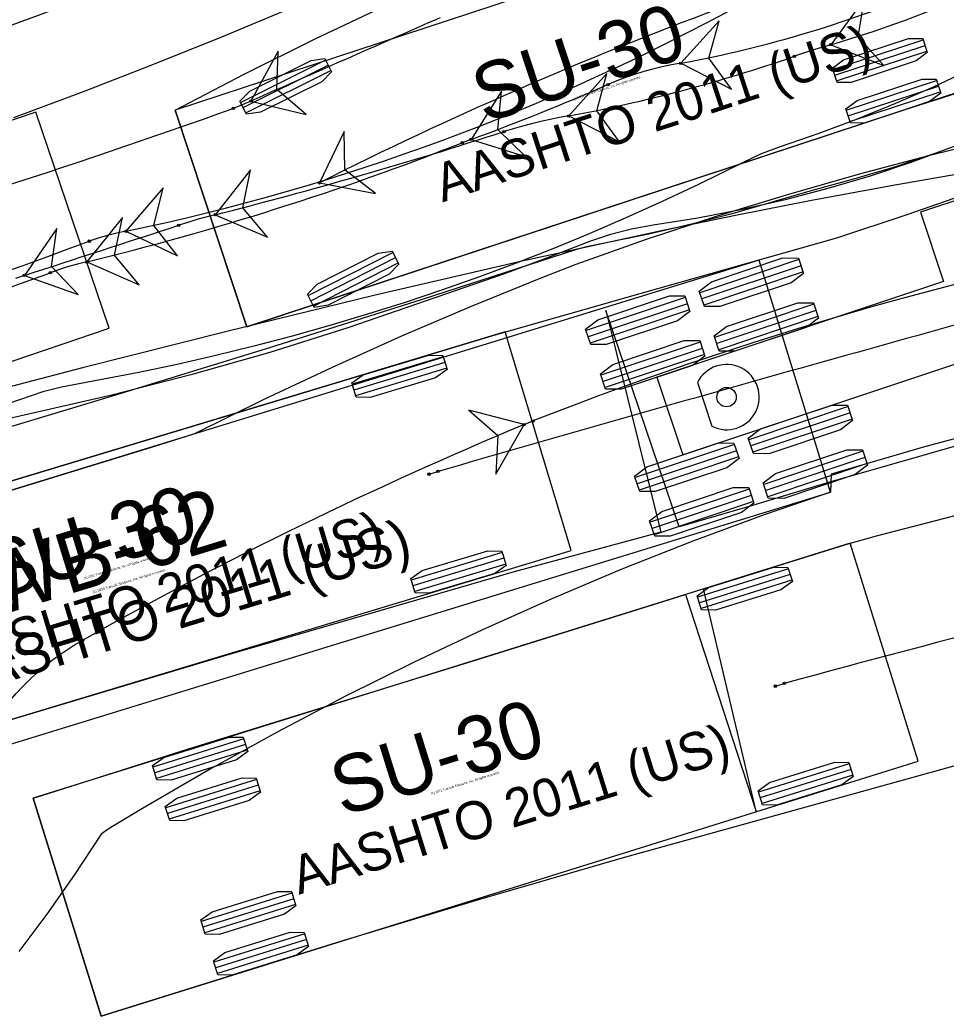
# Model space of a CAD drawing. Extents: x 2096670 to 2098561, y 684033 to 689893.
# Drawn here: x 2097637.92 to 2097670.38, y 685840.48 to 685875.39 of the extents above; entities that cross this region are included whole.
import ezdxf

# ---------------------------------------------------------------- set-up
doc = ezdxf.new("R2010")
doc.units = 0
doc.layers.add('Old_Level_63', color=7, linetype='Continuous')

msp = doc.modelspace()

# ---------------------------------------------------------------- linework, layer by layer
at = {"layer": 'Old_Level_63'}
for p, q in [((2097671.852, 685881.632), (2097643.364, 685872.228)), ((2097666.413, 685873.65), (2097669.578, 685874.695)), ((2097666.478, 685873.452), (2097669.644, 685874.497)), ((2097666.544, 685873.254), (2097669.709, 685874.299)), ((2097645.653, 685872.504), (2097648.635, 685873.995)), ((2097645.746, 685872.318), (2097648.728, 685873.809)), ((2097645.872, 685864.631), (2097674.359, 685874.036)), ((2097645.84, 685872.131), (2097648.821, 685873.622)), ((2097683.714, 685873.402), (2097669.485, 685868.655)), ((2097666.883, 685872.226), (2097670.049, 685873.271)), ((2097666.949, 685872.028), (2097670.114, 685873.073)), ((2097667.014, 685871.83), (2097670.179, 685872.875)), ((2097638.478, 685872.163), (2097610.065, 685862.533)), ((2097641.046, 685864.586), (2097638.478, 685872.163)), ((2097643.364, 685872.228), (2097645.872, 685864.631)), ((2097669.485, 685868.655), (2097670.298, 685866.221)), ((2097648.018, 685865.735), (2097650.989, 685867.246)), ((2097663.828, 685866.968), (2097617.949, 685852.856)), ((2097648.112, 685865.549), (2097651.083, 685867.061)), ((2097648.207, 685865.364), (2097651.178, 685866.875)), ((2097665.226, 685866.993), (2097661.748, 685865.832)), ((2097665.298, 685866.775), (2097661.82, 685865.615)), ((2097666.327, 685858.844), (2097663.828, 685866.968)), ((2097663.828, 685866.968), (2097663.828, 685866.968)), ((2097665.371, 685866.558), (2097661.893, 685865.397)), ((2097670.298, 685866.221), (2097660.242, 685862.866)), ((2097661.242, 685865.663), (2097657.763, 685864.503)), ((2097661.314, 685865.446), (2097657.836, 685864.286)), ((2097665.748, 685865.427), (2097662.27, 685864.267)), ((2097661.387, 685865.229), (2097657.909, 685864.068)), ((2097665.821, 685865.21), (2097662.342, 685864.05)), ((2097665.893, 685864.993), (2097662.415, 685863.832)), ((2097645.872, 685864.631), (2097645.872, 685864.631)), ((2097612.634, 685854.956), (2097641.046, 685864.586)), ((2097654.93, 685864.455), (2097626.208, 685855.794)), ((2097657.24, 685856.796), (2097654.93, 685864.455)), ((2097654.93, 685864.455), (2097654.93, 685864.455)), ((2097661.764, 685864.098), (2097658.286, 685862.938)), ((2097652.757, 685863.582), (2097649.565, 685862.62)), ((2097661.836, 685863.881), (2097658.358, 685862.721)), ((2097661.909, 685863.664), (2097658.431, 685862.503)), ((2097652.817, 685863.383), (2097649.625, 685862.421)), ((2097661.15, 685860.147), (2097671.205, 685863.501)), ((2097652.877, 685863.183), (2097649.685, 685862.221)), ((2097660.242, 685862.866), (2097661.15, 685860.147)), ((2097661.666, 685862.682), (2097662.177, 685861.149)), ((2097666.945, 685861.839), (2097663.467, 685860.678)), ((2097667.018, 685861.621), (2097663.54, 685860.461)), ((2097667.09, 685861.404), (2097663.612, 685860.243)), ((2097662.961, 685860.509), (2097659.483, 685859.349)), ((2097663.034, 685860.292), (2097659.556, 685859.132)), ((2097667.467, 685860.273), (2097663.989, 685859.113)), ((2097663.106, 685860.075), (2097659.628, 685858.914)), ((2097667.54, 685860.056), (2097664.062, 685858.896)), ((2097667.613, 685859.839), (2097664.134, 685858.678)), ((2097620.448, 685844.731), (2097666.327, 685858.844)), ((2097663.483, 685858.944), (2097660.005, 685857.784)), ((2097663.556, 685858.727), (2097660.078, 685857.566)), ((2097663.628, 685858.509), (2097660.15, 685857.349)), ((2097667.021, 685857.05), (2097638.383, 685848.113)), ((2097669.404, 685849.413), (2097667.021, 685857.05)), ((2097667.021, 685857.05), (2097667.021, 685857.05)), ((2097628.517, 685848.135), (2097657.24, 685856.796)), ((2097654.826, 685856.721), (2097651.634, 685855.758)), ((2097654.886, 685856.521), (2097651.694, 685855.559)), ((2097654.946, 685856.322), (2097651.755, 685855.36)), ((2097664.856, 685856.156), (2097661.674, 685855.163)), ((2097664.918, 685855.957), (2097661.736, 685854.964)), ((2097664.98, 685855.758), (2097661.798, 685854.765)), ((2097645.764, 685850.198), (2097642.582, 685849.205)), ((2097645.826, 685849.999), (2097642.644, 685849.006)), ((2097645.888, 685849.8), (2097642.706, 685848.807)), ((2097640.766, 685840.476), (2097669.404, 685849.413)), ((2097666.991, 685849.315), (2097663.809, 685848.322)), ((2097667.053, 685849.116), (2097663.871, 685848.123)), ((2097667.115, 685848.917), (2097663.933, 685847.924)), ((2097646.211, 685848.766), (2097643.029, 685847.773)), ((2097646.273, 685848.567), (2097643.091, 685847.574)), ((2097646.335, 685848.368), (2097643.153, 685847.375)), ((2097638.383, 685848.113), (2097640.766, 685840.476)), ((2097647.452, 685844.788), (2097644.27, 685843.795)), ((2097647.514, 685844.59), (2097644.332, 685843.597)), ((2097647.576, 685844.391), (2097644.394, 685843.398)), ((2097647.899, 685843.357), (2097644.717, 685842.364)), ((2097647.961, 685843.158), (2097644.779, 685842.165)), ((2097648.023, 685842.959), (2097644.841, 685841.966))]:
    msp.add_line(p, q, dxfattribs=at)
for points in [[(2097611.027, 685865.635), (2097616.113, 685867.407), (2097621.195, 685869.216), (2097631.356, 685872.914), (2097644.361, 685877.697), (2097646.901, 685878.659), (2097649.442, 685879.648), (2097654.215, 685881.571), (2097654.52, 685881.765), (2097655.712, 685882.687), (2097656.916, 685883.581), (2097658.129, 685884.446), (2097659.355, 685885.285), (2097660.596, 685886.098), (2097661.228, 685886.456), (2097663.81, 685887.688), (2097665.447, 685888.429), (2097668.097, 685889.57), (2097670.755, 685890.808)], [(2097671.388, 685873.026), (2097668.614, 685872.139), (2097645.872, 685864.631), (2097643.364, 685872.228), (2097645.774, 685873.486), (2097648.27, 685874.728), (2097650.796, 685875.923), (2097653.348, 685877.068), (2097655.81, 685878.116), (2097657.667, 685878.87), (2097660.103, 685879.997), (2097662.573, 685881.082), (2097665.093, 685882.107), (2097666.681, 685882.712), (2097669.252, 685883.626), (2097671.875, 685884.477)], [(2097626.522, 685855.889), (2097654.577, 685864.349), (2097659.655, 685865.807), (2097666.553, 685867.754), (2097669.015, 685868.577), (2097671.467, 685869.43), (2097673.908, 685870.315), (2097676.337, 685871.231), (2097678.755, 685872.178), (2097681.16, 685873.156), (2097683.553, 685874.164), (2097685.932, 685875.203), (2097688.298, 685876.272), (2097690.65, 685877.371), (2097692.988, 685878.5), (2097695.311, 685879.658), (2097697.622, 685880.848), (2097699.9, 685882.058)], [(2097637.708, 685871.968), (2097640.151, 685872.882), (2097642.579, 685873.826), (2097644.994, 685874.802), (2097647.397, 685875.808)], [(2097666.338, 685874.522), (2097668.204, 685873.801), (2097667.298, 685874.804), (2097667.518, 685876.138), (2097666.338, 685874.522)], [(2097661.083, 685873.876), (2097662.863, 685872.963), (2097662.066, 685874.056), (2097662.425, 685875.359), (2097661.083, 685873.876)], [(2097666.338, 685874.522), (2097666.018, 685874.429), (2097665.7, 685874.33), (2097665.383, 685874.227), (2097665.068, 685874.118)], [(2097646.013, 685872.548), (2097647.956, 685872.075), (2097646.928, 685872.952), (2097646.973, 685874.303), (2097646.013, 685872.548)], [(2097661.083, 685873.876), (2097660.755, 685873.817), (2097660.429, 685873.748), (2097660.105, 685873.669), (2097659.783, 685873.581), (2097659.465, 685873.482), (2097659.15, 685873.373), (2097658.839, 685873.254), (2097658.531, 685873.125)], [(2097671.243, 685873.655), (2097669.927, 685873.036), (2097668.61, 685872.46), (2097667.266, 685871.914), (2097665.918, 685871.409), (2097664.567, 685870.943), (2097663.906, 685870.694), (2097663.272, 685870.401), (2097661.708, 685869.628), (2097660.431, 685869.026), (2097659.153, 685868.45), (2097657.874, 685867.899), (2097656.596, 685867.373), (2097655.316, 685866.871), (2097654.026, 685866.39), (2097652.727, 685865.93), (2097651.421, 685865.492), (2097650.107, 685865.075), (2097648.785, 685864.679), (2097647.457, 685864.306), (2097646.122, 685863.954), (2097644.781, 685863.625), (2097643.434, 685863.317), (2097642.086, 685863.033), (2097639.374, 685862.524), (2097638.715, 685862.356), (2097635.843, 685861.37)], [(2097657.157, 685872.027), (2097658.938, 685871.117), (2097658.141, 685872.208), (2097658.496, 685873.512), (2097657.157, 685872.027)], [(2097653.735, 685871.203), (2097655.644, 685870.607), (2097654.673, 685871.548), (2097654.804, 685872.893), (2097653.735, 685871.203)], [(2097646.013, 685872.548), (2097645.708, 685872.413), (2097645.398, 685872.29)], [(2097657.157, 685872.027), (2097656.829, 685871.967), (2097656.502, 685871.901), (2097656.177, 685871.829), (2097655.853, 685871.752), (2097655.53, 685871.667), (2097655.209, 685871.577), (2097654.89, 685871.48)], [(2097609.816, 685850.484), (2097612.285, 685851.185), (2097617.256, 685852.655), (2097642.794, 685860.498), (2097644.054, 685860.899), (2097646.457, 685862.084), (2097648.874, 685863.222), (2097651.305, 685864.315), (2097653.75, 685865.362), (2097656.192, 685866.356), (2097657.414, 685866.834), (2097659.884, 685867.703), (2097662.369, 685868.521), (2097664.87, 685869.29), (2097667.389, 685870.01), (2097669.951, 685870.687), (2097672.53, 685871.313)], [(2097699.852, 685871.449), (2097697.423, 685870.233), (2097694.979, 685869.049), (2097692.521, 685867.895), (2097690.047, 685866.773), (2097687.56, 685865.683), (2097685.058, 685864.625), (2097684.428, 685864.373), (2097666.174, 685859.152), (2097663.602, 685858.37), (2097661.028, 685857.622), (2097658.459, 685865.206), (2097660.383, 685857.44), (2097655.238, 685856.05), (2097645.059, 685853.086), (2097634.895, 685850.058), (2097628.517, 685848.135), (2097626.208, 685855.794), (2097626.522, 685855.889), (2097626.522, 685855.889)], [(2097648.416, 685869.683), (2097650.381, 685869.311), (2097649.309, 685870.134), (2097649.285, 685871.485), (2097648.416, 685869.683)], [(2097671.399, 685871.229), (2097669.99, 685870.706), (2097668.573, 685870.233), (2097667.142, 685869.806), (2097665.684, 685869.419), (2097662.839, 685868.59), (2097661.407, 685868.217), (2097659.964, 685867.879), (2097657.78, 685867.441), (2097657.427, 685867.351), (2097652.017, 685865.598), (2097646.662, 685863.902), (2097641.004, 685862.157), (2097635.721, 685860.567), (2097624.882, 685857.361), (2097614.448, 685854.31), (2097603.853, 685851.239)], [(2097670.627, 685870.948), (2097669.186, 685870.411), (2097667.723, 685869.921), (2097666.24, 685869.479), (2097664.747, 685869.087), (2097663.23, 685868.743), (2097661.682, 685868.446), (2097660.117, 685868.2), (2097659.353, 685868.056), (2097658.622, 685867.869), (2097657.921, 685867.638), (2097656.227, 685866.983), (2097654.863, 685866.479), (2097649.41, 685864.6), (2097646.672, 685863.74), (2097643.914, 685862.955), (2097641.139, 685862.245), (2097637.653, 685861.451), (2097632.385, 685859.681), (2097626.785, 685857.876), (2097621.955, 685856.294), (2097617.307, 685854.818), (2097607.866, 685851.921)], [(2097653.735, 685871.203), (2097653.422, 685871.088)], [(2097671.007, 685870.02), (2097668.46, 685869.577), (2097665.602, 685869.047), (2097663.062, 685868.548), (2097660.515, 685868.025), (2097655.42, 685866.916), (2097650.32, 685865.732), (2097645.215, 685864.488), (2097640.109, 685863.193), (2097634.659, 685861.768), (2097629.517, 685860.389), (2097624.381, 685858.979), (2097619.249, 685857.543), (2097614.121, 685856.081), (2097608.998, 685854.597)], [(2097644.763, 685868.564), (2097646.6, 685867.774), (2097645.732, 685868.81), (2097646.001, 685870.135), (2097644.763, 685868.564)], [(2097641.635, 685867.985), (2097643.438, 685867.119), (2097642.614, 685868.19), (2097642.939, 685869.502), (2097641.635, 685867.985)], [(2097640.263, 685866.913), (2097642.093, 685866.106), (2097641.234, 685867.15), (2097641.516, 685868.472), (2097640.263, 685866.913)], [(2097644.763, 685868.564), (2097644.44, 685868.482), (2097644.118, 685868.393), (2097643.799, 685868.297), (2097643.482, 685868.194)], [(2097638.076, 685866.438), (2097639.96, 685865.768), (2097639.027, 685866.746), (2097639.211, 685868.085), (2097638.076, 685866.438)], [(2097641.635, 685867.985), (2097641.309, 685867.917), (2097640.985, 685867.837), (2097640.665, 685867.744), (2097640.349, 685867.638)], [(2097638.686, 685848.207), (2097643.793, 685849.833), (2097653.955, 685852.972), (2097661.246, 685855.248), (2097663.729, 685847.642), (2097661.881, 685855.446), (2097666.982, 685857.038), (2097667.943, 685857.309), (2097673.099, 685858.643), (2097680.86, 685860.563), (2097685.962, 685862.09), (2097691.057, 685863.643), (2097696.413, 685865.306), (2097698.858, 685866.102), (2097701.265, 685866.944)], [(2097640.263, 685866.913), (2097639.939, 685866.835), (2097639.618, 685866.745), (2097639.3, 685866.644), (2097638.986, 685866.531)], [(2097638.076, 685866.438), (2097637.759, 685866.335)], [(2097655.591, 685861.207), (2097653.658, 685861.72), (2097654.668, 685860.822), (2097654.595, 685859.473), (2097655.591, 685861.207)], [(2097655.591, 685861.207), (2097655.899, 685861.335)], [(2097672.017, 685861.066), (2097669.543, 685860.405), (2097666.349, 685859.467), (2097666.327, 685858.844), (2097664.011, 685858.044), (2097661.508, 685857.12), (2097659.022, 685856.138), (2097656.56, 685855.103), (2097654.127, 685854.017), (2097651.711, 685852.875), (2097649.312, 685851.677), (2097646.93, 685850.424), (2097644.565, 685849.117), (2097642.216, 685847.755), (2097641.048, 685847.055), (2097640.764, 685846.854), (2097639.821, 685845.42), (2097638.859, 685844.05), (2097637.879, 685842.739)], [(2097652.256, 685859.471), (2097652.575, 685859.567)], [(2097703.484, 685858.863), (2097698.012, 685857.136), (2097692.848, 685855.535), (2097687.714, 685853.971), (2097659.06, 685846.025), (2097654.024, 685844.557), (2097648.998, 685843.039), (2097640.766, 685840.476), (2097638.383, 685848.113), (2097638.686, 685848.207), (2097638.686, 685848.207)], [(2097636.607, 685850.172), (2097636.782, 685850.456), (2097636.965, 685850.734), (2097637.158, 685851.006), (2097637.359, 685851.272), (2097637.569, 685851.531), (2097637.788, 685851.783), (2097638.015, 685852.027), (2097638.25, 685852.263), (2097638.494, 685852.49), (2097638.745, 685852.709), (2097639.005, 685852.918), (2097639.272, 685853.117), (2097639.547, 685853.306), (2097639.829, 685853.484), (2097640.118, 685853.65)], [(2097664.394, 685852.04), (2097664.713, 685852.139)]]:
    msp.add_lwpolyline(points, dxfattribs=at)
for points in [[(2097666.338, 685874.522), (2097668.204, 685873.801), (2097667.298, 685874.804), (2097667.518, 685876.138)], [(2097661.083, 685873.876), (2097662.863, 685872.963), (2097662.066, 685874.056), (2097662.425, 685875.359)], [(2097666.56, 685873.205), (2097666.397, 685873.699), (2097666.791, 685873.994), (2097669.07, 685874.747), (2097669.562, 685874.744), (2097669.725, 685874.25), (2097669.331, 685873.955), (2097667.052, 685873.203)], [(2097646.013, 685872.548), (2097647.956, 685872.075), (2097646.928, 685872.952), (2097646.973, 685874.303)], [(2097645.863, 685872.085), (2097645.63, 685872.55), (2097645.977, 685872.899), (2097648.124, 685873.973), (2097648.611, 685874.041), (2097648.844, 685873.576), (2097648.497, 685873.227), (2097646.35, 685872.154)], [(2097657.157, 685872.027), (2097658.938, 685871.117), (2097658.141, 685872.208), (2097658.496, 685873.512)], [(2097667.03, 685871.781), (2097666.867, 685872.275), (2097667.261, 685872.57), (2097669.54, 685873.322), (2097670.032, 685873.32), (2097670.195, 685872.826), (2097669.801, 685872.531), (2097667.522, 685871.778)], [(2097653.735, 685871.203), (2097655.644, 685870.607), (2097654.673, 685871.548), (2097654.804, 685872.893)], [(2097648.416, 685869.683), (2097650.381, 685869.311), (2097649.309, 685870.134), (2097649.285, 685871.485)], [(2097644.763, 685868.564), (2097646.6, 685867.774), (2097645.732, 685868.81), (2097646.001, 685870.135)], [(2097641.635, 685867.985), (2097643.438, 685867.119), (2097642.614, 685868.19), (2097642.939, 685869.502)], [(2097640.263, 685866.913), (2097642.093, 685866.106), (2097641.234, 685867.15), (2097641.516, 685868.472)], [(2097638.076, 685866.438), (2097639.96, 685865.768), (2097639.027, 685866.746), (2097639.211, 685868.085)], [(2097648.23, 685865.318), (2097647.994, 685865.781), (2097648.339, 685866.132), (2097650.478, 685867.22), (2097650.965, 685867.292), (2097651.201, 685866.829), (2097650.856, 685866.478), (2097648.717, 685865.39)], [(2097665.208, 685867.047), (2097665.389, 685866.504), (2097664.956, 685866.178), (2097662.452, 685865.343), (2097661.911, 685865.344), (2097661.73, 685865.886), (2097662.162, 685866.212), (2097664.666, 685867.048)], [(2097661.224, 685865.717), (2097661.405, 685865.175), (2097660.972, 685864.849), (2097658.468, 685864.013), (2097657.927, 685864.014), (2097657.746, 685864.557), (2097658.178, 685864.883), (2097660.682, 685865.718)], [(2097665.73, 685865.481), (2097665.911, 685864.939), (2097665.479, 685864.613), (2097662.974, 685863.777), (2097662.433, 685863.778), (2097662.252, 685864.321), (2097662.684, 685864.647), (2097665.189, 685865.482)], [(2097661.746, 685864.152), (2097661.927, 685863.61), (2097661.495, 685863.284), (2097658.99, 685862.448), (2097658.449, 685862.449), (2097658.268, 685862.992), (2097658.7, 685863.318), (2097661.204, 685864.153)], [(2097652.742, 685863.632), (2097652.892, 685863.134), (2097652.49, 685862.849), (2097650.192, 685862.156), (2097649.7, 685862.172), (2097649.55, 685862.669), (2097649.952, 685862.954), (2097652.25, 685863.647)], [(2097666.927, 685861.892), (2097667.108, 685861.35), (2097666.676, 685861.024), (2097664.172, 685860.188), (2097663.63, 685860.19), (2097663.449, 685860.732), (2097663.882, 685861.058), (2097666.386, 685861.894)], [(2097655.591, 685861.207), (2097653.658, 685861.72), (2097654.668, 685860.822), (2097654.595, 685859.473)], [(2097662.943, 685860.563), (2097663.124, 685860.021), (2097662.692, 685859.695), (2097660.188, 685858.859), (2097659.646, 685858.86), (2097659.465, 685859.403), (2097659.897, 685859.729), (2097662.402, 685860.564)], [(2097667.45, 685860.327), (2097667.631, 685859.785), (2097667.198, 685859.459), (2097664.694, 685858.623), (2097664.152, 685858.624), (2097663.971, 685859.167), (2097664.404, 685859.493), (2097666.908, 685860.328)], [(2097663.465, 685858.998), (2097663.646, 685858.456), (2097663.214, 685858.13), (2097660.71, 685857.294), (2097660.168, 685857.295), (2097659.987, 685857.838), (2097660.42, 685858.164), (2097662.924, 685858.999)], [(2097654.811, 685856.77), (2097654.961, 685856.272), (2097654.559, 685855.988), (2097652.261, 685855.295), (2097651.769, 685855.31), (2097651.619, 685855.808), (2097652.021, 685856.093), (2097654.319, 685856.786)], [(2097664.84, 685856.205), (2097664.995, 685855.709), (2097664.596, 685855.42), (2097662.305, 685854.705), (2097661.813, 685854.716), (2097661.658, 685855.212), (2097662.057, 685855.501), (2097664.348, 685856.216)], [(2097645.748, 685850.247), (2097645.903, 685849.751), (2097645.505, 685849.462), (2097643.214, 685848.747), (2097642.721, 685848.758), (2097642.566, 685849.254), (2097642.965, 685849.543), (2097645.256, 685850.258)], [(2097666.975, 685849.364), (2097667.13, 685848.868), (2097666.731, 685848.579), (2097664.44, 685847.864), (2097663.948, 685847.875), (2097663.793, 685848.371), (2097664.192, 685848.66), (2097666.483, 685849.374)], [(2097646.195, 685848.815), (2097646.35, 685848.319), (2097645.951, 685848.03), (2097643.66, 685847.315), (2097643.168, 685847.326), (2097643.013, 685847.822), (2097643.412, 685848.111), (2097645.703, 685848.826)], [(2097647.437, 685844.838), (2097647.591, 685844.341), (2097647.193, 685844.053), (2097644.902, 685843.338), (2097644.409, 685843.348), (2097644.255, 685843.845), (2097644.653, 685844.133), (2097646.944, 685844.848)], [(2097647.883, 685843.406), (2097648.038, 685842.909), (2097647.64, 685842.621), (2097645.349, 685841.906), (2097644.856, 685841.916), (2097644.701, 685842.413), (2097645.1, 685842.701), (2097647.391, 685843.416)]]:
    msp.add_lwpolyline(points, close=True, dxfattribs=at)
for centre, radius in [((2097666.338, 685874.522), 0.0417), ((2097666.338, 685874.522), 0.0417), ((2097665.068, 685874.118), 0.0417), ((2097665.068, 685874.118), 0.0417), ((2097661.083, 685873.876), 0.0417), ((2097661.083, 685873.876), 0.0417), ((2097658.531, 685873.125), 0.0417), ((2097658.531, 685873.125), 0.0417), ((2097645.398, 685872.29), 0.0417), ((2097645.398, 685872.29), 0.0417), ((2097646.013, 685872.548), 0.0417), ((2097646.013, 685872.548), 0.0417), ((2097657.157, 685872.027), 0.0417), ((2097657.157, 685872.027), 0.0417), ((2097654.89, 685871.48), 0.0417), ((2097654.89, 685871.48), 0.0417), ((2097653.422, 685871.088), 0.0417), ((2097653.422, 685871.088), 0.0417), ((2097653.735, 685871.203), 0.0417), ((2097653.735, 685871.203), 0.0417), ((2097648.416, 685869.683), 0.0417), ((2097644.763, 685868.564), 0.0417), ((2097644.763, 685868.564), 0.0417), ((2097643.482, 685868.194), 0.0417), ((2097643.482, 685868.194), 0.0417), ((2097641.635, 685867.985), 0.0417), ((2097641.635, 685867.985), 0.0417), ((2097640.349, 685867.638), 0.0417), ((2097640.349, 685867.638), 0.0417), ((2097640.263, 685866.913), 0.0417), ((2097640.263, 685866.913), 0.0417), ((2097638.076, 685866.438), 0.0417), ((2097638.076, 685866.438), 0.0417), ((2097638.986, 685866.531), 0.0417), ((2097638.986, 685866.531), 0.0417), ((2097662.688, 685862.171), 0.34), ((2097655.591, 685861.207), 0.0417), ((2097655.591, 685861.207), 0.0417), ((2097655.899, 685861.335), 0.0417), ((2097655.899, 685861.335), 0.0417), ((2097652.256, 685859.471), 0.0417), ((2097652.575, 685859.567), 0.0417), ((2097652.575, 685859.567), 0.0417), ((2097640.118, 685853.65), 0.0417), ((2097640.118, 685853.65), 0.0417), ((2097664.394, 685852.04), 0.0417), ((2097664.713, 685852.139), 0.0417), ((2097664.713, 685852.139), 0.0417)]:
    msp.add_circle(centre, radius, dxfattribs=at)
for centre, radius, start, end in [((2097654.75, 685913.969), 41.114, 286.3716, 303.6828), ((2097653.711, 685914.208), 41, 280.3574, 293.2778), ((2097625.598, 685944.62), 78.294, 281.81956, 298.75351), ((2097709.673, 685748.211), 136.044, 110.314, 116.76117), ((2099190.303, 682373.855), 3824.354, 113.707618, 113.816214), ((2097647.37, 685925.057), 53.926, 280.4564, 289.1587), ((2097622.826, 685955.284), 89.582, 290.18401, 293.48932), ((2097547.762, 686145.929), 290.536, 286.00706, 289.63667), ((2097604.005, 686029.177), 165.704, 284.23893, 287.88367), ((2097616.232, 685965.491), 101.464, 283.70034, 291.50214), ((2096890.725, 688176.118), 2427.582, 287.930202, 288.064366), ((2097702.231, 685743.261), 126.839, 99.55061, 111.42487), ((2097567.896, 686062.099), 207.519, 283.1587, 290.4346), ((2098128.889, 684210.69), 1716.296, 105.203437, 106.112537), ((2097549.186, 686112.867), 262.193, 286.1104, 290.02897), ((2097662.688, 685862.171), 1.143, 243.4496, 153.4496), ((2097711.443, 685727.221), 145.161, 112.62879, 119.42966), ((2097808.796, 685323.307), 548.109, 103.37561, 105.24065)]:
    msp.add_arc(centre, radius, start, end, dxfattribs=at)

# ---------------------------------------------------------------- texts
for s, height, rotation, p in [('SU-30', 2, 18.269, (2097654.199, 685871.761)), ('AASHTO 2011 (US)', 1.33333, 18.269, (2097652.73, 685868.995)), ('(c) 2022 Transoft Solutions, Inc. All rights reserved.', 0.08, 18.269, (2097657.319, 685872.58)), ('SU-30', 2, 16.7802, (2097637.027, 685855.046)), ('WB-62', 2.125, 17.0979, (2097637.011, 685854.45)), ('AASHTO 2011 (US)', 1.33333, 16.7802, (2097635.487, 685852.319)), ('AASHTO 2011 (US)', 1.41667, 17.0979, (2097635.535, 685851.588)), ('(c) 2022 Transoft Solutions, Inc. All rights reserved.', 0.08, 16.7802, (2097640.167, 685855.784)), ('(c) 2023 Transoft Solutions, Inc. All rights reserved.', 0.085, 17.0979, (2097640.487, 685855.297)), ('SU-30', 2, 17.3318, (2097649.209, 685847.469)), ('AASHTO 2011 (US)', 1.33333, 17.3318, (2097647.696, 685844.727)), ('(c) 2022 Transoft Solutions, Inc. All rights reserved.', 0.08, 17.3318, (2097652.342, 685848.237))]:
    msp.add_text(s, height=height, rotation=rotation, dxfattribs=at).set_placement(p)

doc.saveas('drawing.dxf')
